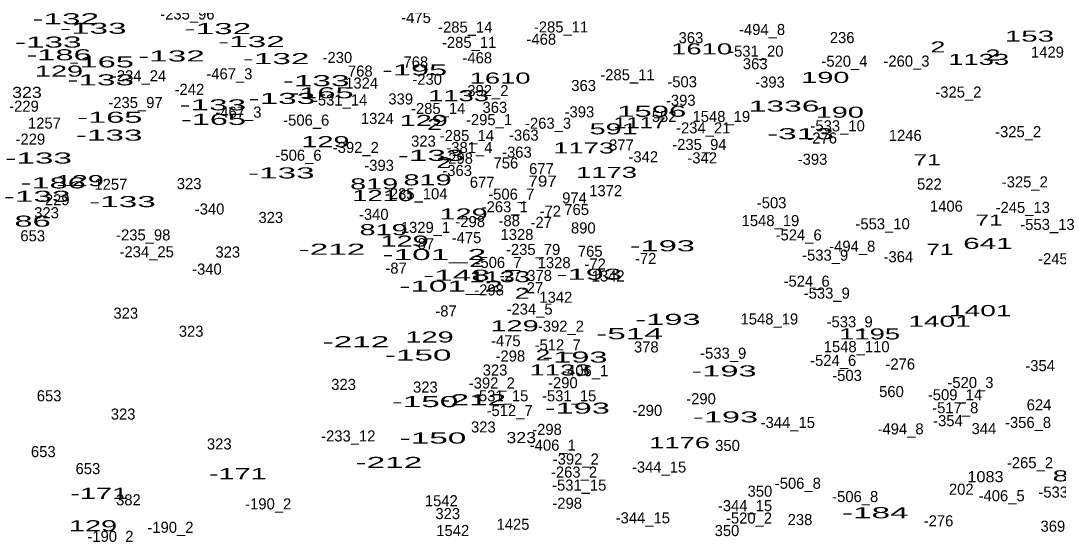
# Model space of a CAD drawing. Extents: x -660434 to -656144, y -997850 to -994016.
# Drawn here: x -658728 to -658353, y -996086 to -995899.8 of the extents above; entities that cross this region are included whole.
import ezdxf
from ezdxf.enums import TextEntityAlignment as Align

# ---------------------------------------------------------------- set-up
doc = ezdxf.new("R2010")
doc.units = 0
doc.header["$LTSCALE"] = 1.6
doc.layers.add('24', color=7, linetype='Continuous')

msp = doc.modelspace()

# ---------------------------------------------------------------- texts
at = {"layer": '24'}
for s, width, p in [('-132', 2.25, (-658711.741, -995901.1)), ('-133', 2.25, (-658701.801, -995904.54)), ('-132', 2.25, (-658656.771, -995904.65)), ('153', 2, (-658363.447, -995907.38)), ('-133', 2.25, (-658718.061, -995909.53)), ('-132', 2.25, (-658644.651, -995909.35)), ('1610', 1.85, (-658481.925, -995911.98)), ('2', 1.8, (-658396.521, -995911.29)), ('-186', 2.2, (-658714.165, -995914.13)), ('-132', 2.25, (-658673.531, -995914.54)), ('-132', 2.25, (-658635.701, -995915.5)), ('1133', 1.85, (-658381.794, -995915.79)), ('2', 1.8, (-658376.651, -995914.21)), ('129', 1.95, (-658714.173, -995920.01)), ('-165', 2.2, (-658698.875, -995916.7)), ('-195', 2.2, (-658585.645, -995919.6)), ('-133', 2.25, (-658699.111, -995923.17)), ('-133', 2.25, (-658621.241, -995923.47)), ('1610', 1.85, (-658554.755, -995922.54)), ('190', 1.95, (-658437.229, -995922.29)), ('323', 1.2, (-658725.76, -995927.7)), ('-165', 2.2, (-658619.475, -995927.84)), ('-133', 2.25, (-658633.631, -995929.89)), ('1133', 1.85, (-658569.774, -995928.88)), ('-133', 2.25, (-658658.601, -995932.2)), ('1596', 2.1, (-658499.967, -995934.53)), ('1336', 2.15, (-658452.113, -995932.65)), ('190', 1.95, (-658431.999, -995934.87)), ('-165', 2.2, (-658695.805, -995936.68)), ('-165', 2.2, (-658658.365, -995937.45)), ('129', 1.95, (-658582.353, -995937.82)), ('1117', 1.6, (-658504.325, -995938.66)), ('2', 1.8, (-658578.451, -995939.25)), ('591', 1.95, (-658513.723, -995940.87)), ('-313', 2.25, (-658446.231, -995942.64)), ('-133', 2.25, (-658696.041, -995943.15)), ('129', 1.95, (-658617.883, -995945.5)), ('1173', 1.85, (-658524.549, -995947.77)), ('-133', 2.25, (-658721.521, -995951.41)), ('-133', 2.25, (-658579.681, -995950.45)), ('2', 1.8, (-658575.191, -995953.08)), ('71', 1.65, (-658400.423, -995952.04)), ('-133', 2.25, (-658633.831, -995956.79)), ('1173', 1.85, (-658516.289, -995956.6)), ('-186', 2.2, (-658716.275, -995960.39)), ('129', 1.95, (-658706.683, -995959.57)), ('819', 1.95, (-658600.283, -995960.74)), ('819', 1.95, (-658580.983, -995959.29)), ('797', 1.15, (-658539.4, -995959.75)), ('-133', 2.25, (-658722.091, -995965.24)), ('1210', 1.85, (-658597.19, -995964.98)), ('-133', 2.25, (-658691.241, -995967.16)), ('129', 1.95, (-658567.953, -995971.62)), ('-186', 2.2, (-658728.955, -995974.22)), ('71', 1.65, (-658378.053, -995973.84)), ('819', 1.95, (-658596.873, -995977.3)), ('129', 1.95, (-658589.273, -995981.42)), ('-193', 2.2, (-658496.125, -995983.12)), ('641', 2, (-658378.458, -995982.25)), ('-212', 2.25, (-658615.511, -995984.37)), ('-101_2', 2.25, (-658578.514, -995986.27)), ('71', 1.65, (-658395.813, -995984.4)), ('2', 1.8, (-658563.181, -995988.77)), ('-148', 2.25, (-658570.536, -995993.77)), ('1133', 1.85, (-658554.894, -995994.29)), ('-193', 2.2, (-658522.525, -995993.39)), ('-101_2', 2.25, (-658572.474, -995997.7)), ('2', 1.8, (-658546.771, -996000.27)), ('1401', 1.9, (-658381.236, -996006.55)), ('-193', 2.2, (-658494.105, -996009.7)), ('1401', 1.9, (-658395.926, -996010.39)), ('129', 1.95, (-658549.523, -996012.02)), ('-212', 2.25, (-658606.871, -996017.79)), ('129', 1.95, (-658580.243, -996016.06)), ('-514', 2.25, (-658507.986, -996014.88)), ('1195', 1.85, (-658421.219, -996014.96)), ('-150', 2.25, (-658584.387, -996022.59)), ('2', 1.8, (-658539.281, -996022.55)), ('-193', 2.2, (-658527.705, -996023.33)), ('1133', 1.85, (-658533.104, -996027.98)), ('-193', 2.2, (-658473.845, -996028.33)), ('-150', 2.25, (-658581.897, -996039.4)), ('-212', 2.25, (-658564.631, -996038.73)), ('-193', 2.2, (-658526.845, -996041.77)), ('-193', 2.2, (-658473.275, -996044.94)), ('-150', 2.25, (-658579.017, -996052.56)), ('323', 1.2, (-658547.12, -996052.41)), ('1176', 1.85, (-658489.903, -996054.25)), ('-212', 2.25, (-658594.961, -996061.39)), ('-171', 1.95, (-658649.561, -996065.44)), ('1083', 1.1, (-658379.34, -996066.53)), ('891', 1.95, (-658346.393, -996066.23)), ('-171', 1.95, (-658699.671, -996072.54)), ('-184', 2.25, (-658419.166, -996079.55)), ('129', 1.95, (-658701.883, -996084.26))]:
    msp.add_text(s, height=4, dxfattribs=dict(at, width=width)).set_placement(p, align=Align.CENTER)
for s, p in [('-235_96', (-658667.782, -995899.38)), ('-475', (-658585.145, -995900.66)), ('-285_14', (-658567.349, -995904.12)), ('-285_11', (-658532.739, -995904.06)), ('-494_8', (-658460.086, -995904.98)), ('-468', (-658539.865, -995908.49)), ('363', (-658485.793, -995907.95)), ('236', (-658431.143, -995907.91)), ('-285_11', (-658565.959, -995909.63)), ('-531_20', (-658462.169, -995912.81)), ('-230', (-658613.579, -995915.09)), ('-468', (-658562.995, -995915.21)), ('-520_4', (-658430.311, -995916.43)), ('-260_3', (-658407.892, -995916.39)), ('1429', (-658356.95, -995913.16)), ('768', (-658605.288, -995920)), ('768', (-658585.228, -995916.73)), ('363', (-658462.563, -995917.35)), ('-234_24', (-658685.25, -995921.72)), ('-467_3', (-658652.598, -995921)), ('-230', (-658581.129, -995922.96)), ('-285_11', (-658508.739, -995921.34)), ('-503', (-658488.969, -995923.85)), ('-393', (-658457.22, -995923.98)), ('-242', (-658667.049, -995926.61)), ('1324', (-658604.804, -995924.33)), ('-392_2', (-658560.058, -995927.04)), ('363', (-658524.583, -995925.23)), ('-325_2', (-658389.132, -995927.58)), ('-235_97', (-658686.533, -995931.36)), ('-531_14', (-658612.583, -995930.45)), ('339', (-658590.683, -995930.07)), ('-393', (-658489.47, -995930.56)), ('-229', (-658726.83, -995932.69)), ('-467_3', (-658649.328, -995934.85)), ('-285_14', (-658577.139, -995933.51)), ('363', (-658556.653, -995933.11)), ('-393', (-658526.1, -995934.73)), ('1257', (-658719.436, -995938.81)), ('-506_6', (-658624.827, -995937.72)), ('1324', (-658599.134, -995937.11)), ('-295_1', (-658558.772, -995937.54)), ('-263_3', (-658537.428, -995938.84)), ('552', (-658495.477, -995936.39)), ('1548_19', (-658474.811, -995936.41)), ('-234_21', (-658481.349, -995940.52)), ('-533_10', (-658432.769, -995939.78)), ('-325_2', (-658367.532, -995941.89)), ('-229', (-658724.53, -995944.6)), ('323', (-658582.467, -995945.31)), ('-285_14', (-658566.769, -995943.3)), ('-363', (-658546.19, -995943.15)), ('377', (-658510.909, -995946.68)), ('-235_94', (-658482.731, -995946.53)), ('-276', (-658438.375, -995944.19)), ('1246', (-658408.34, -995943.25)), ('-506_6', (-658627.607, -995950.4)), ('-392_2', (-658606.898, -995947.59)), ('-381_4', (-658565.87, -995947.63)), ('-363', (-658548.68, -995949.3)), ('-393', (-658598.49, -995954.05)), ('-298', (-658569.94, -995951.51)), ('756', (-658552.678, -995953.2)), ('-342', (-658503.029, -995950.97)), ('-342', (-658481.719, -995951.36)), ('-393', (-658441.86, -995951.85)), ('-363', (-658570.28, -995955.92)), ('677', (-658539.823, -995955.26)), ('1257', (-658695.436, -995960.9)), ('323', (-658667.137, -995960.67)), ('677', (-658561.233, -995960.16)), ('522', (-658399.607, -995960.81)), ('-325_2', (-658365.132, -995960.04)), ('-235_104', (-658585.083, -995964.33)), ('-506_7', (-658550.717, -995964.46)), ('1372', (-658516.606, -995963.21)), ('-229', (-658715.7, -995966.49)), ('-263_1', (-658553.082, -995969.03)), ('974', (-658527.873, -995965.8)), ('-503', (-658456.639, -995967.58)), ('1406', (-658393.464, -995968.8)), ('323', (-658718.657, -995971.17)), ('-340', (-658659.753, -995969.83)), ('323', (-658637.627, -995972.89)), ('-340', (-658600.423, -995971.75)), ('-72', (-658536.631, -995970.6)), ('765', (-658527.098, -995970.02)), ('-245_13', (-658365.869, -995969.26)), ('1329_1', (-658581.728, -995976.47)), ('-298', (-658565.56, -995974.38)), ('-88', (-658551.465, -995974.07)), ('-27', (-658539.901, -995974.64)), ('890', (-658524.697, -995976.67)), ('1548_19', (-658457.061, -995974.02)), ('-553_10', (-658416.519, -995975.18)), ('-553_13', (-658356.945, -995975.41)), ('653', (-658723.673, -995979.51)), ('-235_98', (-658683.727, -995979.19)), ('-475', (-658566.905, -995980.18)), ('1328', (-658548.67, -995979.04)), ('-524_6', (-658446.862, -995979.19)), ('-87', (-658582.481, -995982.37)), ('-494_8', (-658427.496, -995983.28)), ('-234_25', (-658682.486, -995985.28)), ('323', (-658653.177, -995985.37)), ('-235_79', (-658542.833, -995984.45)), ('765', (-658522.198, -995985.09)), ('-72', (-658502.171, -995987.7)), ('-533_9', (-658437.278, -995986.5)), ('-364', (-658410.825, -995987.08)), ('-245_13', (-658350.509, -995987.8)), ('-340', (-658660.713, -995991.54)), ('-87', (-658592.361, -995991.2)), ('-506_7', (-658555.327, -995989.14)), ('1328', (-658535.23, -995989.21)), ('-72', (-658520.411, -995989.71)), ('-27', (-658551.021, -995993.84)), ('378', (-658540.493, -995993.85)), ('1342', (-658515.714, -995994.03)), ('-298', (-658558.74, -995999.06)), ('-27', (-658543.061, -995998.26)), ('-524_6', (-658443.982, -995995.9)), ('1342', (-658534.624, -996001.7)), ('-533_9', (-658436.698, -996000.22)), ('-87', (-658574.311, -996006.66)), ('-234_5', (-658544.097, -996005.99)), ('323', (-658690.047, -996007.46)), ('1548_19', (-658457.441, -996009.55)), ('323', (-658666.427, -996013.99)), ('-392_2', (-658532.788, -996012.16)), ('-533_9', (-658428.438, -996010.58)), ('-475', (-658552.705, -996017.43)), ('-512_7', (-658533.962, -996018.92)), ('378', (-658501.933, -996019.66)), ('1548_110', (-658425.903, -996019.57)), ('-298', (-658551.06, -996022.94)), ('-533_9', (-658474.128, -996021.92)), ('-524_6', (-658434.382, -996024.52)), ('323', (-658556.597, -996028.01)), ('-406_1', (-658524.01, -996028.24)), ('-276', (-658410.135, -996025.82)), ('-354', (-658359.589, -996026.41)), ('-392_2', (-658557.758, -996032.69)), ('-290', (-658532.074, -996032.59)), ('-503', (-658429.369, -996029.95)), ('-520_3', (-658384.776, -996032.52)), ('323', (-658611.327, -996033.2)), ('323', (-658581.757, -996034.16)), ('560', (-658413.327, -996035.77)), ('653', (-658717.743, -996037.3)), ('-531_15', (-658554.379, -996037.31)), ('-531_15', (-658529.809, -996037.32)), ('-290', (-658482.154, -996038.36)), ('-509_14', (-658390.359, -996036.94)), ('323', (-658691.007, -996043.91)), ('-512_7', (-658551.322, -996042.65)), ('-290', (-658501.544, -996042.58)), ('-517_8', (-658390.272, -996041.65)), ('624', (-658359.987, -996040.57)), ('-344_15', (-658450.784, -996046.95)), ('-354', (-658392.909, -996046.29)), ('-356_8', (-658363.958, -996046.93)), ('323', (-658560.827, -996048.57)), ('-298', (-658537.81, -996049.44)), ('-494_8', (-658410.026, -996049.26)), ('344', (-658379.906, -996049.16)), ('323', (-658656.257, -996054.71)), ('-233_12', (-658609.625, -996051.82)), ('-406_1', (-658535.72, -996055.14)), ('350', (-658472.571, -996055.26)), ('653', (-658719.853, -996057.47)), ('-392_2', (-658527.418, -996060.15)), ('-265_2', (-658363.268, -996061.48)), ('653', (-658703.723, -996063.62)), ('-263_2', (-658528.058, -996064.87)), ('-344_15', (-658497.314, -996063.05)), ('-531_15', (-658526.159, -996069.58)), ('-506_8', (-658447.162, -996068.91)), ('350', (-658460.861, -996071.77)), ('-506_8', (-658426.432, -996073.71)), ('202', (-658388.081, -996071.05)), ('-406_5', (-658373.506, -996073.4)), ('-533_1', (-658351.896, -996072.09)), ('382', (-658689.087, -996074.89)), ('-190_2', (-658638.566, -996076.36)), ('1542', (-658576.004, -996075.22)), ('-298', (-658530.52, -996076.11)), ('-344_15', (-658466.244, -996077)), ('323', (-658573.687, -996079.87)), ('-344_15', (-658503.174, -996081.4)), ('-520_2', (-658464.796, -996081.47)), ('-190_2', (-658673.896, -996084.82)), ('1425', (-658550.104, -996083.71)), ('238', (-658446.377, -996082.03)), ('-276', (-658396.315, -996082.48)), ('369', (-658354.988, -996084.42)), ('-190_2', (-658695.586, -996088.08)), ('1542', (-658571.874, -996085.98)), ('350', (-658472.761, -996085.99))]:
    msp.add_text(s, height=4, dxfattribs=at).set_placement(p, align=Align.CENTER)

doc.saveas('drawing.dxf')
